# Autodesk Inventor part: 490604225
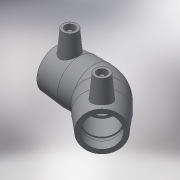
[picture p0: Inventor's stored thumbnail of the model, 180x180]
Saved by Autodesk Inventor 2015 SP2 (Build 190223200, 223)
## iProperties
Created: 2017-06
Part Number: 490604225
Material: Generic
Description: PLASSON 45° ELBOW 225
Document SubType Name: Modeling
Designer: KIM
Mass: 55.0731 g
Surface Area: 148.067 cm^2
Volume: 55.0731 cm^3
Density: 1 g/cm^3
Appearance: Default
Author: KIM
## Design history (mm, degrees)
derived "490604.ipt"
feature "Solid1::490604.ipt"
tag "TaggingFeature1"
body "Solid1"
other parameters: "d2" = 294, "d5" = 264.6, "d8" = 168 deg, "d10" = 48, "d11" = 16, "d14" = 17.6296, "d18" = 225, "d19" = 3.52592, "d20" = 168 deg, "d22" = 270.48, "d23" = 294, "d24" = 262.3656, "d30" = 15, "d31" = 182, "d34" = 5 deg, "d35" = 12, "d39" = 0, "d41" = 4, "d42" = 14, "d43" = 0, "d44" = 9.6, "d45" = 4.8, "d46" = 6, "d47" = 0, "d49" = 225, "d50" = 191.25, "d51" = 48, "d54" = 135 deg, "d65" = 225, "d67" = 45 deg, "d71" = 135 deg, "d75" = 14.7, "d82" = 45 deg, "d84" = 264.6, "d86" = 132.3, "d87" = 135 deg, "d91" = 0, "d93" = 0, "d94" = 135 deg, "d95" = 135.24, "d99" = 176.8, "d101" = 3, "d102" = 0, "d103" = 3, "d104" = 0, "d105" = 34.8, "d106" = 8.7, "d_" = 225, "D_" = 294, "d_2" = 12
